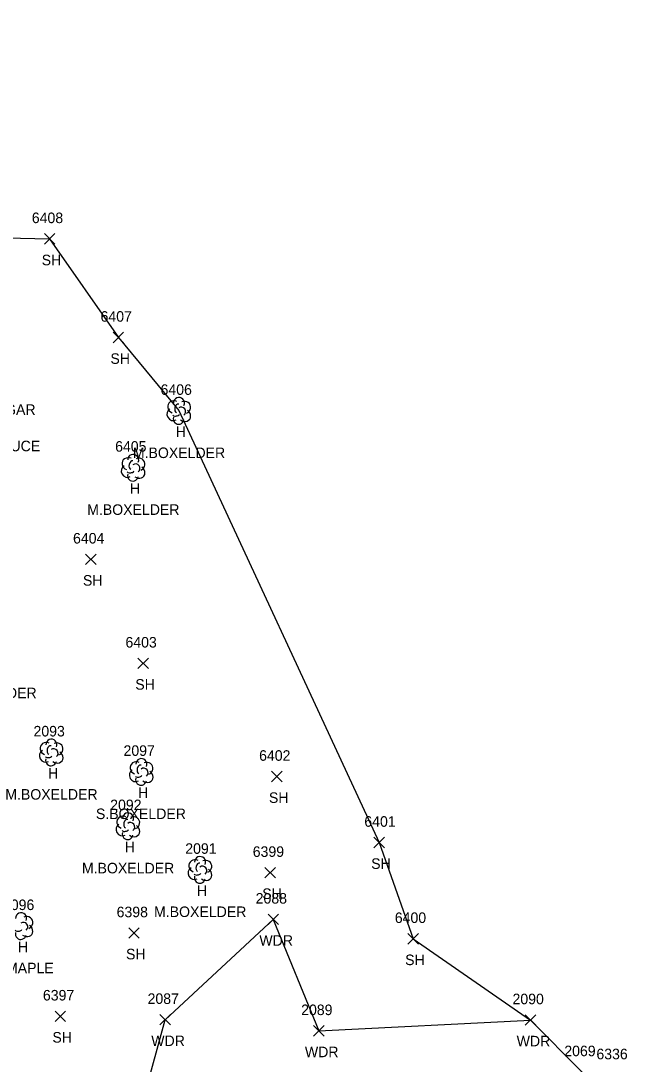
# Model space of a CAD drawing. Extents: x 1439173 to 1457902, y 641926 to 659889.
# Drawn here: x 1449050.9 to 1449166.1, y 643615.4 to 643813.5 of the extents above; entities that cross this region are included whole.
import ezdxf

# ---------------------------------------------------------------- set-up
doc = ezdxf.new("R2010")
doc.units = 0
for name, color, linetype in [('L_A', 7, 'Continuous'), ('L_C', 7, 'Continuous'), ('L_I', 7, 'Continuous'), ('L_TIC', 7, 'Continuous'), ('LAWA', 7, 'Continuous'), ('LSOGP', 7, 'Continuous'), ('LTD', 7, 'Continuous'), ('R_I', 7, 'Continuous')]:
    doc.layers.add(name, color=color, linetype=linetype)

msp = doc.modelspace()

# ---------------------------------------------------------------- linework, layer by layer
at = {"layer": 'L_TIC'}
for points in [[(1449055.4, 643771.14), (1449057.4, 643773.14)], [(1449057.4, 643771.14), (1449055.4, 643773.14)], [(1449068.45, 643752.42), (1449070.45, 643754.42)], [(1449070.45, 643752.42), (1449068.45, 643754.42)], [(1449063.23, 643710.3), (1449065.23, 643712.3)], [(1449065.23, 643710.3), (1449063.23, 643712.3)], [(1449073.18, 643690.55), (1449075.18, 643692.55)], [(1449075.18, 643690.55), (1449073.18, 643692.55)], [(1449098.57, 643669.05), (1449100.57, 643671.05)], [(1449100.57, 643669.05), (1449098.57, 643671.05)], [(1449118, 643656.52), (1449120, 643658.52)], [(1449120, 643656.52), (1449118, 643658.52)], [(1449097.3, 643650.8), (1449099.3, 643652.8)], [(1449099.3, 643650.8), (1449097.3, 643652.8)], [(1449097.88, 643641.93), (1449099.88, 643643.93)], [(1449099.88, 643641.93), (1449097.88, 643643.93)], [(1449071.42, 643639.34), (1449073.42, 643641.34)], [(1449073.42, 643639.34), (1449071.42, 643641.34)], [(1449124.44, 643638.25), (1449126.44, 643640.25)], [(1449126.44, 643638.25), (1449124.44, 643640.25)], [(1449057.43, 643623.53), (1449059.43, 643625.53)], [(1449059.43, 643623.53), (1449057.43, 643625.53)], [(1449077.34, 643622.88), (1449079.34, 643624.88)], [(1449079.34, 643622.88), (1449077.34, 643624.88)], [(1449146.76, 643622.82), (1449148.76, 643624.82)], [(1449148.76, 643622.82), (1449146.76, 643624.82)], [(1449106.53, 643620.76), (1449108.53, 643622.76)], [(1449108.53, 643620.76), (1449106.53, 643622.76)]]:
    msp.add_lwpolyline(points, dxfattribs=at)
at = {"layer": 'LAWA'}
msp.add_lwpolyline([(1449157.56, 643613.95), (1449121.75, 643605.73), (1449092.52, 643598.83), (1449065.07, 643598.44), (1449030.3, 643594.47), (1449023.74, 643594.87), (1449012.82, 643587.98), (1449001.9, 643587.61), (1448999.01, 643594.42), (1449002.01, 643598.82), (1449015.57, 643600.37), (1449033.32, 643605.28), (1449047.53, 643602.79), (1449074.36, 643609.35), (1449074.42, 643609.49), (1449078.34, 643623.88), (1449098.88, 643642.93), (1449107.53, 643621.76), (1449147.76, 643623.82)], dxfattribs=at)
at = {"layer": 'LSOGP'}
msp.add_lwpolyline([(1449015.32, 643815.9), (1449022.77, 643798.58), (1449025.49, 643794.79), (1449025.49, 643794.79), (1449036.96, 643772.58), (1449056.4, 643772.14), (1449069.45, 643753.42), (1449080.91, 643739.53), (1449119, 643657.52), (1449125.44, 643639.25), (1449147.76, 643623.82), (1449157.56, 643613.95)], dxfattribs=at)
at = {"layer": 'LTD'}
for p, q in [((1449080.91, 643739.53), (1449080.91, 643739.53)), ((1449080.91, 643739.53), (1449080.91, 643739.53)), ((1449072.23, 643728.74), (1449072.23, 643728.74)), ((1449072.23, 643728.74), (1449072.23, 643728.74)), ((1449056.67, 643674.67), (1449056.67, 643674.67)), ((1449056.67, 643674.67), (1449056.67, 643674.67)), ((1449073.77, 643670.98), (1449073.77, 643670.98)), ((1449073.77, 643670.98), (1449073.77, 643670.98)), ((1449071.23, 643660.67), (1449071.23, 643660.67)), ((1449071.23, 643660.67), (1449071.23, 643660.67)), ((1449084.93, 643652.38), (1449084.93, 643652.38)), ((1449084.93, 643652.38), (1449084.93, 643652.38)), ((1449050.93, 643641.7), (1449050.93, 643641.7)), ((1449050.93, 643641.7), (1449050.93, 643641.7))]:
    msp.add_line(p, q, dxfattribs=at)
for centre in [(1449080.96, 643740.97), (1449072.27, 643730.18), (1449056.72, 643676.1), (1449073.81, 643672.41), (1449071.28, 643662.1), (1449084.98, 643653.81), (1449050.97, 643643.13)]:
    msp.add_arc(centre, 1.05, 335.5272, 180.9563, dxfattribs=at)
for centre, major_axis, ratio, start_param, end_param in [((1449080.12, 643740.2), (1.21, -0.51), 0.895232, 1.570796, 4.712389), ((1449080.7, 643739.99), (-0.208, -0.792), 0.645439, 3.141593, 6.283185), ((1449081.41, 643739.37), (-0.5, 0.667), 0.989748, 3.141593, 6.283185), ((1449081.95, 643740.12), (-1.14, -0.48), 0.949671, 1.570796, 4.712389), ((1449079.83, 643738.82), (0.58, -1.04), 0.959034, 3.141593, 6.283185), ((1449080.91, 643738.03), (0.26, 1.06), 0.942809, 1.570796, 4.712389), ((1449080.45, 643738.78), (-0.625, -0.083), 0.423636, 0, 3.141593), ((1449081.91, 643738.7), (-1.09, 0.79), 0.841452, 1.570796, 4.712389), ((1449071.44, 643729.41), (1.21, -0.51), 0.895232, 1.570796, 4.712389), ((1449072.02, 643729.2), (-0.208, -0.792), 0.645439, 3.141593, 6.283185), ((1449073.27, 643729.33), (-1.14, -0.48), 0.949671, 1.570796, 4.712389), ((1449071.14, 643728.04), (0.58, -1.04), 0.959034, 3.141593, 6.283185), ((1449072.73, 643728.58), (-0.5, 0.667), 0.989748, 3.141593, 6.283185), ((1449073.23, 643727.91), (-1.09, 0.79), 0.841452, 1.570796, 4.712389), ((1449072.23, 643727.24), (0.26, 1.06), 0.942809, 1.570796, 4.712389), ((1449071.77, 643727.99), (-0.625, -0.083), 0.423636, 0, 3.141593), ((1449055.88, 643675.33), (1.21, -0.51), 0.895232, 1.570796, 4.712389), ((1449057.71, 643675.25), (-1.14, -0.48), 0.949671, 1.570796, 4.712389), ((1449055.59, 643673.96), (0.58, -1.04), 0.959034, 3.141593, 6.283185), ((1449056.46, 643675.12), (-0.208, -0.792), 0.645439, 3.141593, 6.283185), ((1449057.17, 643674.5), (-0.5, 0.667), 0.989748, 3.141593, 6.283185), ((1449057.67, 643673.83), (-1.09, 0.79), 0.841452, 1.570796, 4.712389), ((1449056.67, 643673.17), (0.26, 1.06), 0.942809, 1.570796, 4.712389), ((1449056.21, 643673.92), (-0.625, -0.083), 0.423636, 0, 3.141593), ((1449072.97, 643671.65), (1.21, -0.51), 0.895232, 1.570796, 4.712389), ((1449074.81, 643671.56), (-1.14, -0.48), 0.949671, 1.570796, 4.712389), ((1449072.68, 643670.27), (0.58, -1.04), 0.959034, 3.141593, 6.283185), ((1449073.56, 643671.44), (-0.208, -0.792), 0.645439, 3.141593, 6.283185), ((1449074.27, 643670.81), (-0.5, 0.667), 0.989748, 3.141593, 6.283185), ((1449074.77, 643670.15), (-1.09, 0.79), 0.841452, 1.570796, 4.712389), ((1449073.77, 643669.48), (0.26, 1.06), 0.942809, 1.570796, 4.712389), ((1449073.31, 643670.23), (-0.625, -0.083), 0.423636, 0, 3.141593), ((1449070.15, 643659.96), (0.58, -1.04), 0.959034, 3.141593, 6.283185), ((1449070.44, 643661.33), (1.21, -0.51), 0.895232, 1.570796, 4.712389), ((1449071.03, 643661.13), (-0.208, -0.792), 0.645439, 3.141593, 6.283185), ((1449071.73, 643660.5), (-0.5, 0.667), 0.989748, 3.141593, 6.283185), ((1449072.23, 643659.83), (-1.09, 0.79), 0.841452, 1.570796, 4.712389), ((1449072.28, 643661.25), (-1.14, -0.48), 0.949671, 1.570796, 4.712389), ((1449071.23, 643659.17), (0.26, 1.06), 0.942809, 1.570796, 4.712389), ((1449070.78, 643659.92), (-0.625, -0.083), 0.423636, 0, 3.141593), ((1449084.14, 643653.04), (1.21, -0.51), 0.895232, 1.570796, 4.712389), ((1449084.72, 643652.84), (-0.208, -0.792), 0.645439, 3.141593, 6.283185), ((1449085.43, 643652.21), (-0.5, 0.667), 0.989748, 3.141593, 6.283185), ((1449085.97, 643652.96), (-1.14, -0.48), 0.949671, 1.570796, 4.712389), ((1449083.85, 643651.67), (0.58, -1.04), 0.959034, 3.141593, 6.283185), ((1449084.93, 643650.88), (0.26, 1.06), 0.942809, 1.570796, 4.712389), ((1449084.47, 643651.63), (-0.625, -0.083), 0.423636, 0, 3.141593), ((1449085.93, 643651.55), (-1.09, 0.79), 0.841452, 1.570796, 4.712389), ((1449051.97, 643642.28), (-1.14, -0.48), 0.949671, 1.570796, 4.712389), ((1449050.47, 643640.95), (-0.625, -0.083), 0.423636, 0, 3.141593), ((1449051.43, 643641.53), (-0.5, 0.667), 0.989748, 3.141593, 6.283185), ((1449051.93, 643640.87), (-1.09, 0.79), 0.841452, 1.570796, 4.712389), ((1449050.93, 643640.2), (0.26, 1.06), 0.942809, 1.570796, 4.712389)]:
    msp.add_ellipse(centre, major_axis=major_axis, ratio=ratio, start_param=start_param, end_param=end_param, dxfattribs=at)

# ---------------------------------------------------------------- texts
at = {"layer": 'L_A'}
for s, p in [('SH', (1449054.89, 643767.14)), ('SH', (1449067.94, 643748.42)), ('H', (1449080.35, 643734.53)), ('H', (1449071.66, 643723.74)), ('SH', (1449062.72, 643706.3)), ('SH', (1449072.67, 643686.55)), ('H', (1449056.1, 643669.67)), ('H', (1449073.2, 643665.98)), ('SH', (1449098.06, 643665.05)), ('H', (1449070.67, 643655.67)), ('SH', (1449117.48, 643652.52)), ('H', (1449084.36, 643647.38)), ('SH', (1449096.79, 643646.8)), ('WDR', (1449096.24, 643637.93)), ('H', (1449050.36, 643636.7)), ('SH', (1449070.91, 643635.34)), ('SH', (1449123.93, 643634.25)), ('SH', (1449056.92, 643619.53)), ('WDR', (1449075.7, 643618.88)), ('WDR', (1449145.12, 643618.82)), ('WDR', (1449104.89, 643616.76))]:
    msp.add_text(s, height=2, dxfattribs=at).set_placement(p)
at = {"layer": 'L_C'}
for s, p in [('PORTABLE GAR', (1449032.92, 643738.73)), ('PORTABLE GAR', (1449032.92, 643738.73)), ('S.SPRUCE', (1449040.93, 643731.82)), ('M.BOXELDER', (1449072.21, 643730.53)), ('M.BOXELDER', (1449063.53, 643719.74)), ('M.BOXELDER', (1449036.39, 643684.93)), ('M.BOXELDER', (1449047.97, 643665.67)), ('S.BOXELDER', (1449065.19, 643661.98)), ('M.BOXELDER', (1449062.53, 643651.67)), ('M.BOXELDER', (1449076.23, 643643.38)), ('4S.MAPLE', (1449044.09, 643632.7))]:
    msp.add_text(s, height=2, dxfattribs=at).set_placement(p)
at = {"layer": 'L_I'}
for s, p in [('6408', (1449053.01, 643775.14)), ('6407', (1449066.07, 643756.42)), ('6406', (1449077.47, 643742.53)), ('6405', (1449068.84, 643731.74)), ('6404', (1449060.84, 643714.3)), ('6403', (1449070.8, 643694.55)), ('2093', (1449053.33, 643677.67)), ('2097', (1449070.43, 643673.98)), ('6402', (1449096.19, 643673.05)), ('2092', (1449067.9, 643663.67)), ('6401', (1449116.18, 643660.52)), ('2091', (1449082.16, 643655.38)), ('6399', (1449094.98, 643654.8)), ('2088', (1449095.54, 643645.93)), ('2096', (1449047.53, 643644.7)), ('6398', (1449069.12, 643643.34)), ('6400', (1449121.97, 643642.25)), ('6397', (1449055.12, 643627.53)), ('2087', (1449075, 643626.88)), ('2090', (1449144.33, 643626.82)), ('2089', (1449104.18, 643624.76)), ('2069', (1449154.17, 643616.95))]:
    msp.add_text(s, height=2, dxfattribs=at).set_placement(p)
at = {"layer": 'R_I'}
msp.add_text('6336', height=2, dxfattribs=at).set_placement((1449160.27, 643616.37))

doc.saveas('drawing.dxf')
